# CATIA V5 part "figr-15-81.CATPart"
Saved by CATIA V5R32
Part number: Part1
Bounding box of the stored display mesh (mm): x -28.659 to 28.659, y -52 to 52, z 0 to 2
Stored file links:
  D:\PROJECTS\Project 2022\CATIA V5 6R 2022\Resources\Part Files\c15_catia_v5_6r2022_prt\figr-15-81.CATPart
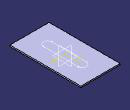
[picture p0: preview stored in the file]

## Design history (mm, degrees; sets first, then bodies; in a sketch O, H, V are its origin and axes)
SheetMetalParameters1: Thickness 2, BendRadius 4, KFactor 0.400515 {= log(min(100,max(20*SheetMetalParameters1.BendRadius,SheetMetalParameters1.Thickness)/SheetMetalParameters1.Thickness))/log(100)/2}, ReliefRadialLength 1, ReliefAxialLength 2, MinimumBendRadius 0
Body1 (main body)
  Sketch1 on xy-plane, origin (0, 0, 0), H (1, 0, 0), V (0, 1, 0)
    line L1 (28.6588, 52) -> (28.6588, -52)
    line L2 (28.6588, -52) -> (-28.6588, -52)
    line L3 (-28.6588, -52) -> (-28.6588, 52)
    line L4 (-28.6588, 52) -> (28.6588, 52)
    vertical: L1 V, L3 V
    horizontal: L2 H, L4 H
    equidistance: L1 L3 O, L2 L4 O
  Wall1: Thickness 2, Profile Sketch1, OffsetValue 0
  Sketch2 on face of Wall1, origin (0, 0, 2), H (1, 0, 0), V (0, 1, 0)
    construction line L1 (0, 25.3065) -> (0, -25.5921)
    point P1 (0, 25.3065)
    line L2 (6, 25.3065) -> (6, -25.5921)
    line L3 (-6, -25.5921) -> (-6, 25.3065)
    arc A1 centre (0, -25.5921) radius 6 from (6, -25.5921) to (-6, -25.5921) cw
    arc A2 centre (0, 25.3065) radius 6 from (-6, 25.3065) to (6, 25.3065) cw
    distance L1 L2 = 6
    coincidence: P1 V
    vertical: L1 V
    tangency: A1 L2, A2 L2, A1 L3, A2 L3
